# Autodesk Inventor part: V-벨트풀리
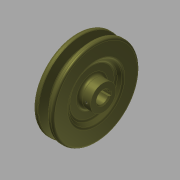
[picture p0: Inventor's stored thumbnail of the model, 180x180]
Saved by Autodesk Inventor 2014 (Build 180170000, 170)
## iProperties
Company: 한국ATC센터
Created: 2015-12
Part Number: V-벨트풀리
Document SubType Name: Modeling
Designer: mdu
Density: 7.25 g/cm^3
Mass: 594.58 g
Surface Area: 210.471 cm^2
Volume: 82.011 cm^3
Material: 주철
Appearance: 티타늄
Author: mdu
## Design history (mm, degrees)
sketch "스케치1"
  geometry: L1 (-13, 0)-(13, 0); L2 (-13, 0)-(-13, 12.5); L3 (-13, 12.5)-(-9, 12.5); L4 (-9, 12.5)-(-9, 23); L5 (-9, 23)-(-13, 27); L6 (-13, 27)-(-13, 42.7); L7 (-13, 42.7)-(-8.325, 42.7); L8 (-8.325, 42.7)-(-5.574, 33.7); L9 (-5.574, 33.7)-(-1.426, 33.7); L10 (-1.426, 33.7)-(1.325, 42.7); L11 (1.325, 42.7)-(6, 42.7); L12 (6, 42.7)-(6, 27); L13 (6, 27)-(2, 23); L14 (2, 23)-(2, 12.5); L15 (2, 12.5)-(13, 12.5); L16 (13, 12.5)-(13, 0); L17 (-7.5, 40)-(0.5, 40); 2 further points
  constraints: 34 end point, 6 parallel, 5 collinear, 5 equal length, 4 perpendicular, 2 point on line, 1 coincident, 1 horizontal, 1 midpoint
  dimensions: "d0" = 26 distance of L1.start L1.end; "d1" = 2.7 distance between parallel lines of L7 L17; "d2" = 6.3 distance between parallel lines of L9 L17; "d3" = 8 distance of L17.start L17.end; "d4" = 34 deg angle of L10 L8; "d5" = 19 distance between parallel lines of L12 L6; "d7" = 25 diameter of L15 L1; "d8" = 46 diameter of L13.end L1; "d9" = 54 diameter of L12.end L1; "d10" = 4 distance between parallel lines of L2 L4; "d11" = 80 diameter of L17 L1
revolve "회전1" sketch "스케치1" stored, may be unused: angle "d12" = 90 deg
sketch "스케치2"
  geometry: L1 (-2, 5.657)-(-2, 7.8); L2 (-2, 7.8)-(2, 7.8); L3 (2, 7.8)-(2, 5.657); A1 r 6 centre (0, 0) between (-2, 5.657) and (2, 5.657); 1 further point
  constraints: 6 end point, 2 parallel, 2 point on circle, 1 centre point, 1 coincident, 1 perpendicular, 1 vertical
  dimensions: "d13" = 12 diameter of A1; "d14" = 13.8 dimension on A1 L2; "d15" = 4 distance of L1.end L2.end
extrude "돌출1" cut sketch "스케치2" stored distance "d16" = 10; taper "d17" = 0 deg
node "작업 평면1"
sketch "스케치3"
  geometry: L1 (-5.5, 12.5)-(-5.5, -12.5) reference; L2 (20.5, 27)-(20.5, -27) reference; 3 further points
  constraints: 1 horizontal alignment, 1 midpoint
  dimensions: "d18" = 4 distance from line of point (-1.5, 0) L1; "d33" = 22 distance from line of point (-1.5, 0) L2 (derived)
hole "구멍1" sketch "스케치3" at (-1.5, 0) diameter "d19" = 2.459; stored, may be unused: countersink angle "d23" = 90 deg, drill point angle "d25" = 118 deg; dims "d20" = 6, "d21" = 4, "d22" = 2, "d24" = 8
fillet "모깎기1" dims "d26" = 2, "d27" = 0.5, "d28" = 1, "d29" = 3
chamfer "모따기1" distance "d30" = 1; stored, may be unused: second distance "d31" = 2, angle "d32" = 45 deg
node "솔리드1"
